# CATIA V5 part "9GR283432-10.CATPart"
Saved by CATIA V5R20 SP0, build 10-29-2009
Part number: 9GR283432-10
Revision: ANY
Definition: UNKNOWN
Nomenclature: 9GR283432-10
Source: Unknown
Bounding box of the stored display mesh (mm): x -15.967 to 16, y -29 to 5, z -16 to 16
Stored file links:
  C:\Users\Utente\Desktop\IO LAVORO\3D X SITO CF\CUMSA\3D files GR\GR 283432-10\9GR283432-10.CATPart
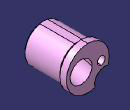
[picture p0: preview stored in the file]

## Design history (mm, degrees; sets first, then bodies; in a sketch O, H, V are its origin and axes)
Body1 "Cortar-Extruir7" (main body)
  Solid1: solid without history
